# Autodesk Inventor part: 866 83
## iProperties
Created: 2005-11
Part Number: 866 83
Material: 1.4301 X5CrNi10-10 A2
Description: Flansch KF 25 (lang)
Document SubType Name: Modellieren
Designer: Mittelmeyer
Manufacturer: Standard
Standards Organization: Custom
Author: Mittelmeyer
Comments: LEYBOLD
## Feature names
1. Extrusion2
2. Drehung1 [Revolution]
3. Bohrung1 [Hole]
